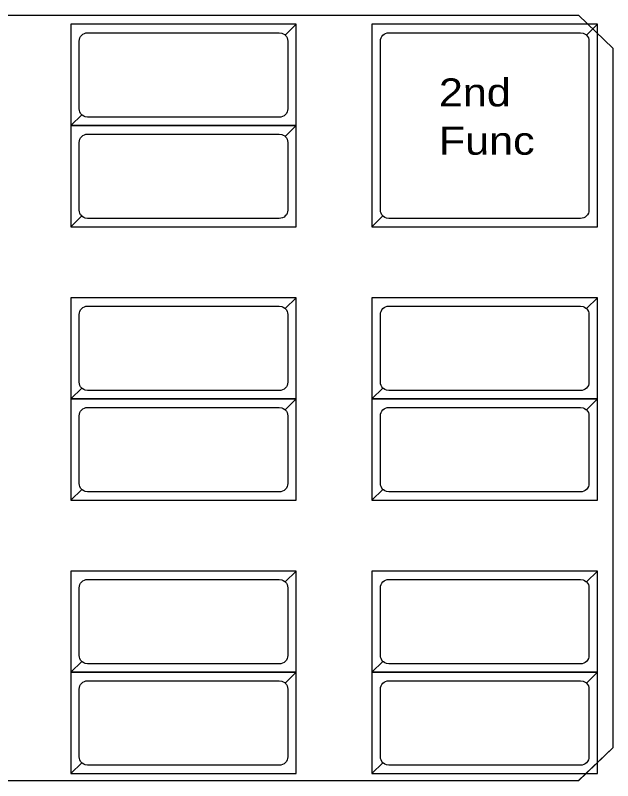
# Model space of a CAD drawing. Extents: x 16898 to 16911.6, y 15837.8 to 15842.
# Drawn here: x 16909.975 to 16911.567, y 15837.832 to 15839.872 of the extents above; entities that cross this region are included whole.
import ezdxf

# ---------------------------------------------------------------- set-up
doc = ezdxf.new("R2010")
doc.units = 0
doc.header["$LTSCALE"] = 0.018
doc.layers.add('1', color=7, linetype='Continuous', lineweight=25)
doc.layers.add('2', color=7, linetype='Continuous', lineweight=13)

msp = doc.modelspace()

# ---------------------------------------------------------------- linework, layer by layer
at = {"layer": '1'}
for points in [[(16897.9955, 15837.8322), (16897.9955, 15839.8723), (16911.4764, 15839.8723), (16911.5674, 15839.785), (16911.5674, 15837.9198), (16911.4764, 15837.8322)], [(16910.1229, 15839.5783), (16910.7238, 15839.5783), (16910.7238, 15839.8483), (16910.1229, 15839.8483)], [(16910.1229, 15839.5783), (16910.7238, 15839.5783), (16910.7238, 15839.8483), (16910.6947, 15839.8192), (16910.6975, 15839.8158), (16910.6996, 15839.8119), (16910.7008, 15839.8077), (16910.7013, 15839.8033), (16910.7013, 15839.6233), (16910.7008, 15839.6189), (16910.6996, 15839.6147), (16910.6975, 15839.6108), (16910.6947, 15839.6074), (16910.6947, 15839.6074), (16910.6913, 15839.6046), (16910.6874, 15839.6025), (16910.6832, 15839.6012), (16910.6788, 15839.6008), (16910.1679, 15839.6008), (16910.1613, 15839.6018), (16910.1573, 15839.6035), (16910.1536, 15839.6059), (16910.152, 15839.6074)], [(16910.7238, 15839.8483), (16910.1229, 15839.8483), (16910.1229, 15839.5783), (16910.152, 15839.6074), (16910.1492, 15839.6108), (16910.1471, 15839.6147), (16910.1458, 15839.6189), (16910.1454, 15839.6233), (16910.1454, 15839.8033), (16910.1458, 15839.8077), (16910.1471, 15839.8119), (16910.1492, 15839.8158), (16910.152, 15839.8192), (16910.152, 15839.8192), (16910.1554, 15839.822), (16910.1593, 15839.8241), (16910.1635, 15839.8253), (16910.1679, 15839.8258), (16910.6788, 15839.8258), (16910.6854, 15839.8248), (16910.6894, 15839.8231), (16910.6931, 15839.8207), (16910.6947, 15839.8192)], [(16910.9258, 15839.3083), (16911.5267, 15839.3083), (16911.5267, 15839.8483), (16910.9258, 15839.8483)], [(16910.9258, 15839.3083), (16911.5267, 15839.3083), (16911.5267, 15839.8483), (16911.4976, 15839.8192), (16911.5004, 15839.8158), (16911.5025, 15839.8119), (16911.5037, 15839.8077), (16911.5042, 15839.8033), (16911.5042, 15839.3533), (16911.5037, 15839.3489), (16911.5025, 15839.3447), (16911.5004, 15839.3408), (16911.4976, 15839.3374), (16911.4976, 15839.3374), (16911.4942, 15839.3346), (16911.4903, 15839.3325), (16911.4861, 15839.3312), (16911.4817, 15839.3308), (16910.9708, 15839.3308), (16910.9642, 15839.3318), (16910.9602, 15839.3335), (16910.9565, 15839.3359), (16910.9549, 15839.3374)], [(16911.5267, 15839.8483), (16910.9258, 15839.8483), (16910.9258, 15839.3083), (16910.9549, 15839.3374), (16910.9521, 15839.3408), (16910.95, 15839.3447), (16910.9487, 15839.3489), (16910.9483, 15839.3533), (16910.9483, 15839.8033), (16910.9487, 15839.8077), (16910.95, 15839.8119), (16910.9521, 15839.8158), (16910.9549, 15839.8192), (16910.9549, 15839.8192), (16910.9583, 15839.822), (16910.9622, 15839.8241), (16910.9664, 15839.8253), (16910.9708, 15839.8258), (16911.4817, 15839.8258), (16911.4883, 15839.8248), (16911.4923, 15839.8231), (16911.496, 15839.8207), (16911.4976, 15839.8192)], [(16910.1229, 15839.3083), (16910.7238, 15839.3083), (16910.7238, 15839.5783), (16910.1229, 15839.5783)], [(16910.1229, 15839.3083), (16910.7238, 15839.3083), (16910.7238, 15839.5783), (16910.6947, 15839.5492), (16910.6975, 15839.5458), (16910.6996, 15839.5419), (16910.7008, 15839.5377), (16910.7013, 15839.5333), (16910.7013, 15839.3533), (16910.7008, 15839.3489), (16910.6996, 15839.3447), (16910.6975, 15839.3408), (16910.6947, 15839.3374), (16910.6947, 15839.3374), (16910.6913, 15839.3346), (16910.6874, 15839.3325), (16910.6832, 15839.3312), (16910.6788, 15839.3308), (16910.1679, 15839.3308), (16910.1613, 15839.3318), (16910.1573, 15839.3335), (16910.1536, 15839.3359), (16910.152, 15839.3374)], [(16910.7238, 15839.5783), (16910.1229, 15839.5783), (16910.1229, 15839.3083), (16910.152, 15839.3374), (16910.1492, 15839.3408), (16910.1471, 15839.3447), (16910.1458, 15839.3489), (16910.1454, 15839.3533), (16910.1454, 15839.5333), (16910.1458, 15839.5377), (16910.1471, 15839.5419), (16910.1492, 15839.5458), (16910.152, 15839.5492), (16910.152, 15839.5492), (16910.1554, 15839.552), (16910.1593, 15839.5541), (16910.1635, 15839.5553), (16910.1679, 15839.5558), (16910.6788, 15839.5558), (16910.6854, 15839.5548), (16910.6894, 15839.5531), (16910.6931, 15839.5507), (16910.6947, 15839.5492)], [(16910.1229, 15838.8496), (16910.7238, 15838.8496), (16910.7238, 15839.1196), (16910.1229, 15839.1196)], [(16910.1229, 15838.8496), (16910.7238, 15838.8496), (16910.7238, 15839.1196), (16910.6947, 15839.0905), (16910.6975, 15839.0871), (16910.6996, 15839.0832), (16910.7008, 15839.079), (16910.7013, 15839.0746), (16910.7013, 15838.8946), (16910.7008, 15838.8902), (16910.6996, 15838.886), (16910.6975, 15838.8821), (16910.6947, 15838.8787), (16910.6947, 15838.8787), (16910.6913, 15838.8759), (16910.6874, 15838.8738), (16910.6832, 15838.8725), (16910.6788, 15838.8721), (16910.1679, 15838.8721), (16910.1613, 15838.8731), (16910.1573, 15838.8748), (16910.1536, 15838.8772), (16910.152, 15838.8787)], [(16910.7238, 15839.1196), (16910.1229, 15839.1196), (16910.1229, 15838.8496), (16910.152, 15838.8787), (16910.1492, 15838.8821), (16910.1471, 15838.886), (16910.1458, 15838.8902), (16910.1454, 15838.8946), (16910.1454, 15839.0746), (16910.1458, 15839.079), (16910.1471, 15839.0832), (16910.1492, 15839.0871), (16910.152, 15839.0905), (16910.152, 15839.0905), (16910.1554, 15839.0933), (16910.1593, 15839.0954), (16910.1635, 15839.0966), (16910.1679, 15839.0971), (16910.6788, 15839.0971), (16910.6854, 15839.0961), (16910.6894, 15839.0944), (16910.6931, 15839.092), (16910.6947, 15839.0905)], [(16910.9258, 15838.8496), (16911.5267, 15838.8496), (16911.5267, 15839.1196), (16910.9258, 15839.1196)], [(16910.9258, 15838.8496), (16911.5267, 15838.8496), (16911.5267, 15839.1196), (16911.4976, 15839.0905), (16911.5004, 15839.0871), (16911.5025, 15839.0832), (16911.5037, 15839.079), (16911.5042, 15839.0746), (16911.5042, 15838.8946), (16911.5037, 15838.8902), (16911.5025, 15838.886), (16911.5004, 15838.8821), (16911.4976, 15838.8787), (16911.4976, 15838.8787), (16911.4942, 15838.8759), (16911.4903, 15838.8738), (16911.4861, 15838.8725), (16911.4817, 15838.8721), (16910.9708, 15838.8721), (16910.9642, 15838.8731), (16910.9602, 15838.8748), (16910.9565, 15838.8772), (16910.9549, 15838.8787)], [(16911.5267, 15839.1196), (16910.9258, 15839.1196), (16910.9258, 15838.8496), (16910.9549, 15838.8787), (16910.9521, 15838.8821), (16910.95, 15838.886), (16910.9487, 15838.8902), (16910.9483, 15838.8946), (16910.9483, 15839.0746), (16910.9487, 15839.079), (16910.95, 15839.0832), (16910.9521, 15839.0871), (16910.9549, 15839.0905), (16910.9549, 15839.0905), (16910.9583, 15839.0933), (16910.9622, 15839.0954), (16910.9664, 15839.0966), (16910.9708, 15839.0971), (16911.4817, 15839.0971), (16911.4883, 15839.0961), (16911.4923, 15839.0944), (16911.496, 15839.092), (16911.4976, 15839.0905)], [(16910.1229, 15838.5796), (16910.7238, 15838.5796), (16910.7238, 15838.8496), (16910.1229, 15838.8496)], [(16910.1229, 15838.5796), (16910.7238, 15838.5796), (16910.7238, 15838.8496), (16910.6947, 15838.8205), (16910.6975, 15838.8171), (16910.6996, 15838.8132), (16910.7008, 15838.809), (16910.7013, 15838.8046), (16910.7013, 15838.6246), (16910.7008, 15838.6202), (16910.6996, 15838.616), (16910.6975, 15838.6121), (16910.6947, 15838.6087), (16910.6947, 15838.6087), (16910.6913, 15838.6059), (16910.6874, 15838.6038), (16910.6832, 15838.6025), (16910.6788, 15838.6021), (16910.1679, 15838.6021), (16910.1613, 15838.6031), (16910.1573, 15838.6048), (16910.1536, 15838.6072), (16910.152, 15838.6087)], [(16910.7238, 15838.8496), (16910.1229, 15838.8496), (16910.1229, 15838.5796), (16910.152, 15838.6087), (16910.1492, 15838.6121), (16910.1471, 15838.616), (16910.1458, 15838.6202), (16910.1454, 15838.6246), (16910.1454, 15838.8046), (16910.1458, 15838.809), (16910.1471, 15838.8132), (16910.1492, 15838.8171), (16910.152, 15838.8205), (16910.152, 15838.8205), (16910.1554, 15838.8233), (16910.1593, 15838.8254), (16910.1635, 15838.8266), (16910.1679, 15838.8271), (16910.6788, 15838.8271), (16910.6854, 15838.8261), (16910.6894, 15838.8244), (16910.6931, 15838.822), (16910.6947, 15838.8205)], [(16910.9258, 15838.5796), (16911.5267, 15838.5796), (16911.5267, 15838.8496), (16910.9258, 15838.8496)], [(16910.9258, 15838.5796), (16911.5267, 15838.5796), (16911.5267, 15838.8496), (16911.4976, 15838.8205), (16911.5004, 15838.8171), (16911.5025, 15838.8132), (16911.5037, 15838.809), (16911.5042, 15838.8046), (16911.5042, 15838.6246), (16911.5037, 15838.6202), (16911.5025, 15838.616), (16911.5004, 15838.6121), (16911.4976, 15838.6087), (16911.4976, 15838.6087), (16911.4942, 15838.6059), (16911.4903, 15838.6038), (16911.4861, 15838.6025), (16911.4817, 15838.6021), (16910.9708, 15838.6021), (16910.9642, 15838.6031), (16910.9602, 15838.6048), (16910.9565, 15838.6072), (16910.9549, 15838.6087)], [(16911.5267, 15838.8496), (16910.9258, 15838.8496), (16910.9258, 15838.5796), (16910.9549, 15838.6087), (16910.9521, 15838.6121), (16910.95, 15838.616), (16910.9487, 15838.6202), (16910.9483, 15838.6246), (16910.9483, 15838.8046), (16910.9487, 15838.809), (16910.95, 15838.8132), (16910.9521, 15838.8171), (16910.9549, 15838.8205), (16910.9549, 15838.8205), (16910.9583, 15838.8233), (16910.9622, 15838.8254), (16910.9664, 15838.8266), (16910.9708, 15838.8271), (16911.4817, 15838.8271), (16911.4883, 15838.8261), (16911.4923, 15838.8244), (16911.496, 15838.822), (16911.4976, 15838.8205)], [(16910.1229, 15838.1211), (16910.7238, 15838.1211), (16910.7238, 15838.3911), (16910.1229, 15838.3911)], [(16910.1229, 15838.1211), (16910.7238, 15838.1211), (16910.7238, 15838.3911), (16910.6947, 15838.362), (16910.6975, 15838.3586), (16910.6996, 15838.3547), (16910.7008, 15838.3505), (16910.7013, 15838.3461), (16910.7013, 15838.1661), (16910.7008, 15838.1617), (16910.6996, 15838.1575), (16910.6975, 15838.1536), (16910.6947, 15838.1502), (16910.6947, 15838.1502), (16910.6913, 15838.1474), (16910.6874, 15838.1453), (16910.6832, 15838.144), (16910.6788, 15838.1436), (16910.1679, 15838.1436), (16910.1613, 15838.1446), (16910.1573, 15838.1463), (16910.1536, 15838.1487), (16910.152, 15838.1502)], [(16910.7238, 15838.3911), (16910.1229, 15838.3911), (16910.1229, 15838.1211), (16910.152, 15838.1502), (16910.1492, 15838.1536), (16910.1471, 15838.1575), (16910.1458, 15838.1617), (16910.1454, 15838.1661), (16910.1454, 15838.3461), (16910.1458, 15838.3505), (16910.1471, 15838.3547), (16910.1492, 15838.3586), (16910.152, 15838.362), (16910.152, 15838.362), (16910.1554, 15838.3648), (16910.1593, 15838.3669), (16910.1635, 15838.3681), (16910.1679, 15838.3686), (16910.6788, 15838.3686), (16910.6854, 15838.3676), (16910.6894, 15838.3659), (16910.6931, 15838.3635), (16910.6947, 15838.362)], [(16910.9258, 15838.1211), (16911.5267, 15838.1211), (16911.5267, 15838.3911), (16910.9258, 15838.3911)], [(16910.9258, 15838.1211), (16911.5267, 15838.1211), (16911.5267, 15838.3911), (16911.4976, 15838.362), (16911.5004, 15838.3586), (16911.5025, 15838.3547), (16911.5037, 15838.3505), (16911.5042, 15838.3461), (16911.5042, 15838.1661), (16911.5037, 15838.1617), (16911.5025, 15838.1575), (16911.5004, 15838.1536), (16911.4976, 15838.1502), (16911.4976, 15838.1502), (16911.4942, 15838.1474), (16911.4903, 15838.1453), (16911.4861, 15838.144), (16911.4817, 15838.1436), (16910.9708, 15838.1436), (16910.9642, 15838.1446), (16910.9602, 15838.1463), (16910.9565, 15838.1487), (16910.9549, 15838.1502)], [(16911.5267, 15838.3911), (16910.9258, 15838.3911), (16910.9258, 15838.1211), (16910.9549, 15838.1502), (16910.9521, 15838.1536), (16910.95, 15838.1575), (16910.9487, 15838.1617), (16910.9483, 15838.1661), (16910.9483, 15838.3461), (16910.9487, 15838.3505), (16910.95, 15838.3547), (16910.9521, 15838.3586), (16910.9549, 15838.362), (16910.9549, 15838.362), (16910.9583, 15838.3648), (16910.9622, 15838.3669), (16910.9664, 15838.3681), (16910.9708, 15838.3686), (16911.4817, 15838.3686), (16911.4883, 15838.3676), (16911.4923, 15838.3659), (16911.496, 15838.3635), (16911.4976, 15838.362)], [(16910.1229, 15837.8511), (16910.7238, 15837.8511), (16910.7238, 15838.1211), (16910.1229, 15838.1211)], [(16910.1229, 15837.8511), (16910.7238, 15837.8511), (16910.7238, 15838.1211), (16910.6947, 15838.092), (16910.6975, 15838.0886), (16910.6996, 15838.0847), (16910.7008, 15838.0805), (16910.7013, 15838.0761), (16910.7013, 15837.8961), (16910.7008, 15837.8917), (16910.6996, 15837.8875), (16910.6975, 15837.8836), (16910.6947, 15837.8802), (16910.6947, 15837.8802), (16910.6913, 15837.8774), (16910.6874, 15837.8753), (16910.6832, 15837.874), (16910.6788, 15837.8736), (16910.1679, 15837.8736), (16910.1613, 15837.8746), (16910.1573, 15837.8763), (16910.1536, 15837.8787), (16910.152, 15837.8802)], [(16910.7238, 15838.1211), (16910.1229, 15838.1211), (16910.1229, 15837.8511), (16910.152, 15837.8802), (16910.1492, 15837.8836), (16910.1471, 15837.8875), (16910.1458, 15837.8917), (16910.1454, 15837.8961), (16910.1454, 15838.0761), (16910.1458, 15838.0805), (16910.1471, 15838.0847), (16910.1492, 15838.0886), (16910.152, 15838.092), (16910.152, 15838.092), (16910.1554, 15838.0948), (16910.1593, 15838.0969), (16910.1635, 15838.0981), (16910.1679, 15838.0986), (16910.6788, 15838.0986), (16910.6854, 15838.0976), (16910.6894, 15838.0959), (16910.6931, 15838.0935), (16910.6947, 15838.092)], [(16910.9258, 15837.8511), (16911.5267, 15837.8511), (16911.5267, 15838.1211), (16910.9258, 15838.1211)], [(16910.9258, 15837.8511), (16911.5267, 15837.8511), (16911.5267, 15838.1211), (16911.4976, 15838.092), (16911.5004, 15838.0886), (16911.5025, 15838.0847), (16911.5037, 15838.0805), (16911.5042, 15838.0761), (16911.5042, 15837.8961), (16911.5037, 15837.8917), (16911.5025, 15837.8875), (16911.5004, 15837.8836), (16911.4976, 15837.8802), (16911.4976, 15837.8802), (16911.4942, 15837.8774), (16911.4903, 15837.8753), (16911.4861, 15837.874), (16911.4817, 15837.8736), (16910.9708, 15837.8736), (16910.9642, 15837.8746), (16910.9602, 15837.8763), (16910.9565, 15837.8787), (16910.9549, 15837.8802)], [(16911.5267, 15838.1211), (16910.9258, 15838.1211), (16910.9258, 15837.8511), (16910.9549, 15837.8802), (16910.9521, 15837.8836), (16910.95, 15837.8875), (16910.9487, 15837.8917), (16910.9483, 15837.8961), (16910.9483, 15838.0761), (16910.9487, 15838.0805), (16910.95, 15838.0847), (16910.9521, 15838.0886), (16910.9549, 15838.092), (16910.9549, 15838.092), (16910.9583, 15838.0948), (16910.9622, 15838.0969), (16910.9664, 15838.0981), (16910.9708, 15838.0986), (16911.4817, 15838.0986), (16911.4883, 15838.0976), (16911.4923, 15838.0959), (16911.496, 15838.0935), (16911.4976, 15838.092)]]:
    msp.add_lwpolyline(points, close=True, dxfattribs=at)
at = {"layer": '2'}
msp.add_lwpolyline([(16897.9955, 15837.8324), (16897.9955, 15839.8723), (16911.4764, 15839.8723), (16911.5674, 15839.785), (16911.5674, 15837.9197), (16911.4764, 15837.8324)], close=True, dxfattribs=at)

# ---------------------------------------------------------------- texts
at = {"layer": '1', "width": 1.15}
for s, p in [('2nd', (16911.1042, 15839.6295)), ('Func', (16911.1042, 15839.5007))]:
    msp.add_text(s, height=0.07461, dxfattribs=at).set_placement(p)

doc.saveas('drawing.dxf')
